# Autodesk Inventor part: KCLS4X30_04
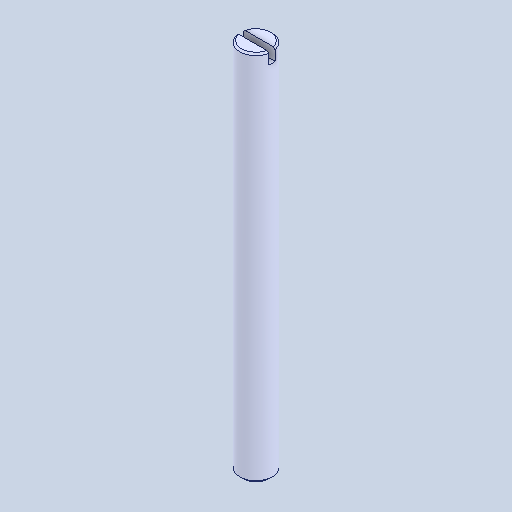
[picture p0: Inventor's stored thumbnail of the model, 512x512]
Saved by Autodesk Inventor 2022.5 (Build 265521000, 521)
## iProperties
Created: 2024-08
Part Number: KCLS4X30_04
Material: 一般
Document SubType Name: Modeling
Designer: ImaoCorp
Density: 1 g/cm^3
Appearance: 既定
Author: ImaoCorp
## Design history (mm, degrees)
feature "KCLS4X30_04"
node "ソリッド1"
